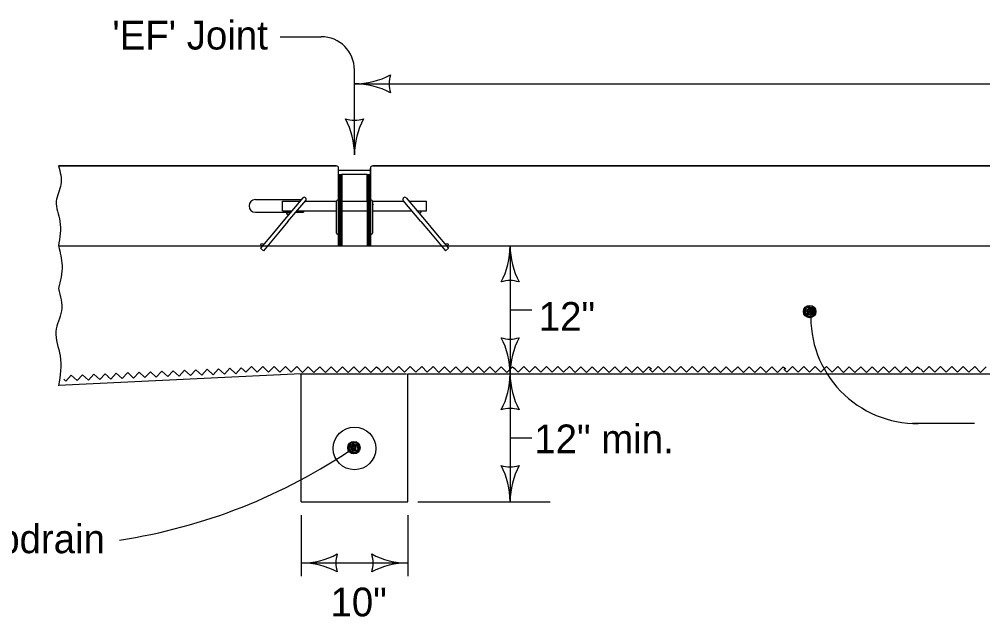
# Model space of a CAD drawing. Extents: x -2135039 to -2124495, y -2139046 to -2132546.
# Drawn here: x -2130571 to -2130034, y -2133912 to -2133579 of the extents above; entities that cross this region are included whole.
import ezdxf

# ---------------------------------------------------------------- set-up
doc = ezdxf.new("R2010")
doc.units = 0
doc.layers.add('BridgeSuperStructureExisting', color=7, linetype='Continuous')
doc.layers.add('dsnStdLabel', color=7, linetype='Continuous')

msp = doc.modelspace()

# ---------------------------------------------------------------- linework, layer by layer
at = {"layer": 'BridgeSuperStructureExisting'}
for p, q in [((-2130425.44, -2133589.02), (-2130402.65, -2133589.02)), ((-2130384.09, -2133622.52), (-2130384.09, -2133607.59)), ((-2130384.09, -2133615.29), (-2129457.45, -2133615.29)), ((-2130384.09, -2133654.91), (-2130384.09, -2133622.52)), ((-2130394.24, -2133661.05), (-2130549.09, -2133661.05)), ((-2130549.09, -2133661.05), (-2130394.24, -2133661.05)), ((-2130393, -2133680.62), (-2130393, -2133662.3)), ((-2130393, -2133692.06), (-2130393, -2133662.3)), ((-2130393, -2133663.46), (-2130375.18, -2133663.46)), ((-2130375.18, -2133662.3), (-2130375.18, -2133680.65)), ((-2130375.18, -2133692.06), (-2130375.18, -2133662.3)), ((-2129457.45, -2133661.05), (-2130373.93, -2133661.05)), ((-2130373.93, -2133661.05), (-2129457.45, -2133661.05)), ((-2130393, -2133665.86), (-2130391.21, -2133665.86)), ((-2130392.82, -2133665.86), (-2130392.82, -2133692.06)), ((-2130392.64, -2133665.86), (-2130392.64, -2133692.06)), ((-2130392.46, -2133665.86), (-2130392.46, -2133692.06)), ((-2130392.28, -2133665.86), (-2130392.28, -2133692.06)), ((-2130392.11, -2133665.86), (-2130392.11, -2133692.06)), ((-2130391.93, -2133665.86), (-2130391.93, -2133692.06)), ((-2130391.75, -2133665.86), (-2130391.75, -2133692.06)), ((-2130391.57, -2133665.86), (-2130391.57, -2133692.06)), ((-2130391.39, -2133665.86), (-2130391.39, -2133692.06)), ((-2130391.21, -2133665.86), (-2130391.21, -2133680.65)), ((-2130376.96, -2133665.86), (-2130391.21, -2133665.86)), ((-2130391.21, -2133665.86), (-2130391.21, -2133680.65)), ((-2130376.96, -2133665.86), (-2130376.96, -2133680.65)), ((-2130376.96, -2133680.65), (-2130376.96, -2133665.86)), ((-2130376.96, -2133665.86), (-2130375.18, -2133665.86)), ((-2130376.78, -2133665.86), (-2130376.78, -2133692.06)), ((-2130376.6, -2133665.86), (-2130376.6, -2133692.06)), ((-2130376.42, -2133665.86), (-2130376.42, -2133692.06)), ((-2130376.25, -2133665.86), (-2130376.25, -2133692.06)), ((-2130376.07, -2133665.86), (-2130376.07, -2133692.06)), ((-2130375.89, -2133665.86), (-2130375.89, -2133692.06)), ((-2130375.71, -2133665.86), (-2130375.71, -2133692.06)), ((-2130375.53, -2133665.86), (-2130375.53, -2133692.06)), ((-2130375.35, -2133665.86), (-2130375.35, -2133692.06)), ((-2130439.33, -2133679.76), (-2130413.63, -2133679.76)), ((-2130424.18, -2133686), (-2130424.18, -2133680.65)), ((-2130424.18, -2133680.65), (-2130414.38, -2133680.65)), ((-2130412.91, -2133678.9), (-2130423.95, -2133692.06)), ((-2130421.16, -2133692.06), (-2130411.27, -2133680.27)), ((-2130414.38, -2133680.65), (-2130414.38, -2133680.65)), ((-2130411.59, -2133680.65), (-2130394.07, -2133680.65)), ((-2130394.07, -2133698.47), (-2130394.07, -2133680.65)), ((-2130394.06, -2133698.47), (-2130394.06, -2133680.65)), ((-2130393.53, -2133680.12), (-2130393.53, -2133680.12)), ((-2130391.21, -2133680.65), (-2130391.21, -2133686)), ((-2130391.21, -2133680.65), (-2130376.96, -2133680.65)), ((-2130376.96, -2133680.65), (-2130376.96, -2133686)), ((-2130374.11, -2133680.65), (-2130374.11, -2133698.47)), ((-2130374.11, -2133698.47), (-2130374.11, -2133680.65)), ((-2130374.11, -2133680.65), (-2130356.58, -2133680.65)), ((-2130347.02, -2133692.06), (-2130356.9, -2133680.27)), ((-2130355.27, -2133678.9), (-2130344.22, -2133692.06)), ((-2130353.79, -2133680.65), (-2130353.79, -2133680.65)), ((-2130353.79, -2133680.65), (-2130343.99, -2133680.65)), ((-2130343.99, -2133686), (-2130343.99, -2133680.65)), ((-2130424.18, -2133686), (-2130418.86, -2133686)), ((-2130416.08, -2133686), (-2130394.07, -2133686)), ((-2130412.6, -2133686), (-2130412.6, -2133686.89)), ((-2130391.21, -2133686), (-2130376.96, -2133686)), ((-2130391.21, -2133686), (-2130391.21, -2133692.06)), ((-2130376.96, -2133686), (-2130376.96, -2133692.06)), ((-2130374.11, -2133681.36), (-2130374.11, -2133681.36)), ((-2130374.11, -2133686), (-2130352.1, -2133686)), ((-2130349.31, -2133686), (-2130343.99, -2133686)), ((-2130439.33, -2133686.89), (-2130419.62, -2133686.89)), ((-2130416.82, -2133686.89), (-2130412.6, -2133686.89)), ((-2130423.95, -2133692.06), (-2130429.21, -2133698.32)), ((-2130421.16, -2133692.06), (-2130426.42, -2133698.32)), ((-2130393, -2133698.32), (-2130393, -2133692.06)), ((-2130392.82, -2133692.06), (-2130392.82, -2133698.32)), ((-2130392.64, -2133692.06), (-2130392.64, -2133698.32)), ((-2130392.46, -2133692.06), (-2130392.46, -2133698.32)), ((-2130392.28, -2133692.06), (-2130392.28, -2133698.32)), ((-2130392.11, -2133692.06), (-2130392.11, -2133698.32)), ((-2130391.93, -2133692.06), (-2130391.93, -2133698.32)), ((-2130391.75, -2133692.06), (-2130391.75, -2133698.32)), ((-2130391.57, -2133692.06), (-2130391.57, -2133698.32)), ((-2130391.39, -2133692.06), (-2130391.39, -2133698.32)), ((-2130391.21, -2133692.06), (-2130391.21, -2133698.32)), ((-2130376.96, -2133692.06), (-2130376.96, -2133698.32)), ((-2130376.78, -2133692.06), (-2130376.78, -2133698.32)), ((-2130376.6, -2133692.06), (-2130376.6, -2133698.32)), ((-2130376.42, -2133692.06), (-2130376.42, -2133698.32)), ((-2130376.25, -2133692.06), (-2130376.25, -2133698.32)), ((-2130376.07, -2133692.06), (-2130376.07, -2133698.32)), ((-2130375.89, -2133692.06), (-2130375.89, -2133698.32)), ((-2130375.71, -2133692.06), (-2130375.71, -2133698.32)), ((-2130375.53, -2133692.06), (-2130375.53, -2133698.32)), ((-2130375.35, -2133692.06), (-2130375.35, -2133698.32)), ((-2130375.18, -2133698.32), (-2130375.18, -2133692.06)), ((-2130347.02, -2133692.06), (-2130341.75, -2133698.32)), ((-2130344.22, -2133692.06), (-2130338.97, -2133698.32)), ((-2130429.21, -2133698.32), (-2130436.45, -2133706.96)), ((-2130426.42, -2133698.32), (-2130434.81, -2133708.33)), ((-2130394.07, -2133698.47), (-2130394.07, -2133698.47)), ((-2130393, -2133705.6), (-2130393, -2133698.32)), ((-2130393, -2133705.6), (-2130393, -2133698.51)), ((-2130392.82, -2133698.32), (-2130392.82, -2133705.6)), ((-2130392.64, -2133698.32), (-2130392.64, -2133705.6)), ((-2130392.46, -2133698.32), (-2130392.46, -2133705.6)), ((-2130392.28, -2133698.32), (-2130392.28, -2133705.6)), ((-2130392.11, -2133698.32), (-2130392.11, -2133705.6)), ((-2130391.93, -2133698.32), (-2130391.93, -2133705.6)), ((-2130391.75, -2133698.32), (-2130391.75, -2133705.6)), ((-2130391.57, -2133698.32), (-2130391.57, -2133705.6)), ((-2130391.39, -2133698.32), (-2130391.39, -2133705.6)), ((-2130391.21, -2133698.32), (-2130391.21, -2133705.6)), ((-2130376.96, -2133698.32), (-2130376.96, -2133705.6)), ((-2130376.78, -2133698.32), (-2130376.78, -2133705.6)), ((-2130376.6, -2133698.32), (-2130376.6, -2133705.6)), ((-2130376.42, -2133698.32), (-2130376.42, -2133705.6)), ((-2130376.25, -2133698.32), (-2130376.25, -2133705.6)), ((-2130376.07, -2133698.32), (-2130376.07, -2133705.6)), ((-2130375.89, -2133698.32), (-2130375.89, -2133705.6)), ((-2130375.71, -2133698.32), (-2130375.71, -2133705.6)), ((-2130375.53, -2133698.32), (-2130375.53, -2133705.6)), ((-2130375.35, -2133698.32), (-2130375.35, -2133705.6)), ((-2130375.18, -2133705.6), (-2130375.18, -2133698.32)), ((-2130375.18, -2133698.47), (-2130375.18, -2133705.6)), ((-2130341.75, -2133698.32), (-2130333.36, -2133708.33)), ((-2130338.97, -2133698.32), (-2130331.72, -2133706.96)), ((-2130549.09, -2133705.6), (-2130432.52, -2133705.6)), ((-2130549.09, -2133705.6), (-2130435.31, -2133705.6)), ((-2130434.81, -2133708.33), (-2130436.45, -2133706.96)), ((-2130432.52, -2133705.6), (-2130393, -2133705.6)), ((-2130432.52, -2133705.6), (-2130391.21, -2133705.6)), ((-2130391.21, -2133705.6), (-2130376.96, -2133705.6)), ((-2130376.96, -2133705.6), (-2130335.65, -2133705.6)), ((-2130375.18, -2133705.6), (-2130332.86, -2133705.6)), ((-2130333.36, -2133708.33), (-2130331.72, -2133706.96)), ((-2130332.86, -2133705.6), (-2129457.45, -2133705.6)), ((-2130332.86, -2133705.6), (-2129457.45, -2133705.6)), ((-2130297.35, -2133705.6), (-2130297.35, -2133776.88)), ((-2130297.35, -2133741.24), (-2130285.23, -2133741.24)), ((-2130413.79, -2133776.88), (-2130549.09, -2133783.44)), ((-2130414.41, -2133776.88), (-2130355.01, -2133776.88)), ((-2130413.79, -2133848.16), (-2130413.79, -2133776.88)), ((-2130354.39, -2133776.88), (-2129457.45, -2133776.88)), ((-2130354.39, -2133848.16), (-2130354.39, -2133776.88)), ((-2130297.35, -2133776.88), (-2130297.35, -2133848.16)), ((-2130038.53, -2133804.61), (-2130073.08, -2133804.61)), ((-2130297.35, -2133812.52), (-2130285.23, -2133812.52)), ((-2130413.79, -2133848.16), (-2130354.39, -2133848.16)), ((-2130348.81, -2133848.16), (-2130275.01, -2133848.16)), ((-2130413.79, -2133855.59), (-2130413.79, -2133889.74)), ((-2130354.39, -2133855.59), (-2130354.39, -2133889.74)), ((-2130413.79, -2133882.32), (-2130354.39, -2133882.32))]:
    msp.add_line(p, q, dxfattribs=at)
for points in [[(-2130391.21, -2133666), (-2130391.07, -2133665.86)], [(-2130375.18, -2133680.65), (-2130375.18, -2133680.65)], [(-2130391.21, -2133686.29), (-2130390.92, -2133686)], [(-2130375.18, -2133698.47), (-2130375.18, -2133698.47)], [(-2130130.12, -2133745.4), (-2130131.29, -2133744.87), (-2130133.11, -2133744.31), (-2130133.46, -2133742.46), (-2130133.21, -2133740.84), (-2130132.05, -2133739.35), (-2130130.32, -2133739.5), (-2130128.49, -2133739.75), (-2130127.62, -2133741.21), (-2130127.46, -2133742.74), (-2130128.53, -2133744.75), (-2130129.86, -2133744.91), (-2130131.68, -2133744.45), (-2130133.18, -2133743.29), (-2130133.13, -2133741.56), (-2130131.97, -2133740.16), (-2130130.33, -2133740.01), (-2130128.51, -2133740.36), (-2130128.23, -2133741.39), (-2130127.86, -2133742.62), (-2130128.72, -2133744.13), (-2130130.05, -2133744.09), (-2130131.57, -2133743.84), (-2130132.66, -2133743), (-2130132.11, -2133741.48), (-2130130.96, -2133740.6), (-2130129.43, -2133740.54), (-2130129.05, -2133741.36), (-2130128.56, -2133742.3), (-2130129.32, -2133743.5), (-2130130.44, -2133743.77), (-2130131.45, -2133743.23), (-2130131.52, -2133742.11), (-2130130.98, -2133741.31), (-2130129.96, -2133741.03), (-2130129.46, -2133741.46), (-2130129.17, -2133742.08), (-2130129.7, -2133742.98), (-2130130.43, -2133743.16), (-2130131.13, -2133742.74), (-2130131.01, -2133742.13), (-2130130.49, -2133741.73), (-2130129.78, -2133741.75), (-2130129.79, -2133742.26), (-2130130.41, -2133742.55)], [(-2130546.19, -2133779.89), (-2130545.03, -2133780.95), (-2130542.01, -2133777.65), (-2130538.7, -2133780.68), (-2130535.67, -2133777.37), (-2130532.37, -2133780.4), (-2130529.34, -2133777.1), (-2130526.04, -2133780.13), (-2130523.01, -2133776.84), (-2130521.37, -2133778.34)], [(-2130521.52, -2133778.32), (-2130519.87, -2133779.83), (-2130516.85, -2133776.54), (-2130513.54, -2133779.57), (-2130510.51, -2133776.25), (-2130507.22, -2133779.29), (-2130504.18, -2133775.99), (-2130500.88, -2133779.01), (-2130497.85, -2133775.72), (-2130494.55, -2133778.74), (-2130491.52, -2133775.44), (-2130488.22, -2133778.47), (-2130485.2, -2133775.16), (-2130481.89, -2133778.19), (-2130478.86, -2133774.89), (-2130475.57, -2133777.92), (-2130472.53, -2133774.62), (-2130469.23, -2133777.65), (-2130466.21, -2133774.34), (-2130462.9, -2133777.38), (-2130459.87, -2133774.07), (-2130456.57, -2133777.09), (-2130453.54, -2133773.8), (-2130450.24, -2133776.82), (-2130447.21, -2133773.53), (-2130445.57, -2133775.04)], [(-2130446.28, -2133774.39), (-2130444.7, -2133775.99), (-2130441.52, -2133772.82), (-2130438.36, -2133776), (-2130435.18, -2133772.84), (-2130432.02, -2133776.02), (-2130428.85, -2133772.86), (-2130425.69, -2133776.04), (-2130422.51, -2133772.88), (-2130419.35, -2133776.06), (-2130416.17, -2133772.89), (-2130413.01, -2133776.07), (-2130409.84, -2133772.91), (-2130406.68, -2133776.09), (-2130403.5, -2133772.93), (-2130400.34, -2133776.1), (-2130397.17, -2133772.94), (-2130394.01, -2133776.12), (-2130390.84, -2133772.96), (-2130387.67, -2133776.14), (-2130384.49, -2133772.98), (-2130381.34, -2133776.15), (-2130378.16, -2133772.99), (-2130375, -2133776.18), (-2130371.83, -2133773.01), (-2130370.4, -2133774.14)], [(-2130370.41, -2133774.39), (-2130368.83, -2133775.99), (-2130365.65, -2133772.82), (-2130362.49, -2133776), (-2130359.31, -2133772.84), (-2130356.15, -2133776.02), (-2130352.98, -2133772.86), (-2130349.82, -2133776.04), (-2130346.64, -2133772.88), (-2130343.49, -2133776.06), (-2130340.3, -2133772.89), (-2130337.14, -2133776.07), (-2130333.97, -2133772.91), (-2130330.81, -2133776.09), (-2130327.63, -2133772.93), (-2130324.47, -2133776.1), (-2130321.3, -2133772.94), (-2130318.14, -2133776.12), (-2130314.97, -2133772.96), (-2130311.81, -2133776.14), (-2130308.62, -2133772.98), (-2130305.47, -2133776.15), (-2130302.3, -2133772.99), (-2130299.13, -2133776.18), (-2130295.96, -2133773.01), (-2130294.53, -2133774.14)], [(-2130294.44, -2133774.39), (-2130292.86, -2133775.99), (-2130289.68, -2133772.82), (-2130286.53, -2133776), (-2130283.34, -2133772.84), (-2130280.18, -2133776.02), (-2130277.01, -2133772.86), (-2130273.85, -2133776.04), (-2130270.67, -2133772.88), (-2130267.52, -2133776.06), (-2130264.33, -2133772.89), (-2130261.17, -2133776.07), (-2130258, -2133772.91), (-2130254.85, -2133776.09), (-2130251.66, -2133772.93), (-2130248.5, -2133776.1), (-2130245.33, -2133772.94), (-2130242.17, -2133776.12), (-2130239, -2133772.96), (-2130235.84, -2133776.14), (-2130232.65, -2133772.98), (-2130229.5, -2133776.15), (-2130226.33, -2133772.99), (-2130223.17, -2133776.18), (-2130219.99, -2133773.01), (-2130218.56, -2133774.14)], [(-2130219.6, -2133774.39), (-2130218.02, -2133775.99), (-2130214.84, -2133772.82), (-2130211.68, -2133776), (-2130208.5, -2133772.84), (-2130205.34, -2133776.02), (-2130202.17, -2133772.86), (-2130199.01, -2133776.04), (-2130195.83, -2133772.88), (-2130192.67, -2133776.06), (-2130189.49, -2133772.89), (-2130186.33, -2133776.07), (-2130183.16, -2133772.91), (-2130180, -2133776.09), (-2130176.82, -2133772.93), (-2130173.66, -2133776.1), (-2130170.49, -2133772.94), (-2130167.33, -2133776.12), (-2130164.16, -2133772.96), (-2130160.99, -2133776.14), (-2130157.81, -2133772.98), (-2130154.66, -2133776.15), (-2130151.48, -2133772.99), (-2130148.32, -2133776.18), (-2130145.15, -2133773.01), (-2130143.72, -2133774.14)], [(-2130144.7, -2133774.39), (-2130143.13, -2133775.99), (-2130139.94, -2133772.82), (-2130136.79, -2133776), (-2130133.61, -2133772.84), (-2130130.45, -2133776.02), (-2130127.28, -2133772.86), (-2130124.12, -2133776.04), (-2130120.94, -2133772.88), (-2130117.78, -2133776.06), (-2130114.6, -2133772.89), (-2130111.44, -2133776.07), (-2130108.26, -2133772.91), (-2130105.11, -2133776.09), (-2130101.93, -2133772.93), (-2130098.77, -2133776.1), (-2130095.6, -2133772.94), (-2130092.44, -2133776.12), (-2130089.26, -2133772.96), (-2130086.1, -2133776.14), (-2130082.92, -2133772.98), (-2130079.77, -2133776.15), (-2130076.59, -2133772.99), (-2130073.43, -2133776.18), (-2130070.26, -2133773.01), (-2130068.83, -2133774.14)], [(-2130068.48, -2133774.39), (-2130066.9, -2133775.99), (-2130063.72, -2133772.82), (-2130060.57, -2133776), (-2130057.38, -2133772.84), (-2130054.22, -2133776.02), (-2130051.06, -2133772.86), (-2130047.9, -2133776.04), (-2130044.71, -2133772.88), (-2130041.56, -2133776.06), (-2130038.38, -2133772.89), (-2130035.22, -2133776.07), (-2130032.04, -2133772.91)], [(-2130384.67, -2133821.24), (-2130383.49, -2133820.71), (-2130381.68, -2133820.15), (-2130381.32, -2133818.3), (-2130381.58, -2133816.69), (-2130382.74, -2133815.19), (-2130384.47, -2133815.34), (-2130386.29, -2133815.6), (-2130387.17, -2133817.05), (-2130387.33, -2133818.58), (-2130386.25, -2133820.59), (-2130384.92, -2133820.76), (-2130383.1, -2133820.29), (-2130381.61, -2133819.13), (-2130381.66, -2133817.4), (-2130382.82, -2133816.01), (-2130384.45, -2133815.85), (-2130386.27, -2133816.21), (-2130386.55, -2133817.24), (-2130386.92, -2133818.47), (-2130386.07, -2133819.98), (-2130384.74, -2133819.94), (-2130383.22, -2133819.69), (-2130382.12, -2133818.84), (-2130382.68, -2133817.33), (-2130383.83, -2133816.44), (-2130385.36, -2133816.39), (-2130385.74, -2133817.21), (-2130386.22, -2133818.14), (-2130385.47, -2133819.34), (-2130384.34, -2133819.62), (-2130383.34, -2133819.08), (-2130383.27, -2133817.96), (-2130383.8, -2133817.16), (-2130384.83, -2133816.88), (-2130385.33, -2133817.3), (-2130385.62, -2133817.92), (-2130385.08, -2133818.82), (-2130384.36, -2133819.01), (-2130383.66, -2133818.58), (-2130383.78, -2133817.97), (-2130384.3, -2133817.58), (-2130385.01, -2133817.6), (-2130385, -2133818.11), (-2130384.38, -2133818.4)]]:
    msp.add_lwpolyline(points, dxfattribs=at)
for centre, radius in [((-2130347.78, -2133686.71), 0.713), ((-2130421.14, -2133687.6), 0.713), ((-2130435.65, -2133704.89), 0.713), ((-2130332.53, -2133704.89), 0.713), ((-2130130.39, -2133742.22), 3.46), ((-2130384.09, -2133818.46), 11.88), ((-2130384.4, -2133818.06), 3.46)]:
    msp.add_circle(centre, radius, dxfattribs=at)
for centre, radius, start, end in [((-2130402.65, -2133607.58), 18.56, 0, 90), ((-2130384.09, -2133572.54), 42.75, 270, 298.0725), ((-2130348.24, -2133615.28), 16.51, 162.2666, 197.7334), ((-2130384.09, -2133658.03), 42.75, 61.9275, 90), ((-2130384.09, -2133619.06), 16.51, 252.2666, 287.7333), ((-2130426.83, -2133654.9), 42.75, 360, 28.0725), ((-2130341.34, -2133654.9), 42.75, 151.9275, 180), ((-2130394.24, -2133662.3), 1.25, 360, 90), ((-2130394.24, -2133662.3), 1.25, 0, 90), ((-2130373.93, -2133662.3), 1.25, 90, 180), ((-2130373.93, -2133662.3), 1.25, 90, 180), ((-2130439.33, -2133683.32), 3.56, 90, 270), ((-2130412.09, -2133679.58), 1.07, 320.0037, 139.9964), ((-2130393.53, -2133680.65), 0.535, 3.7252, 180), ((-2130393.53, -2133680.65), 0.535, 0, 180), ((-2130393.53, -2133680.65), 0.535, 0, 180), ((-2130374.64, -2133680.65), 0.535, 0, 180), ((-2130374.64, -2133680.65), 0.535, 0, 180), ((-2130356.08, -2133679.58), 1.07, 40.0036, 219.9963), ((-2130393.53, -2133698.47), 0.535, 180, 355.2519), ((-2130393.53, -2133698.47), 0.535, 180, 0), ((-2130374.64, -2133698.47), 0.535, 180, 0), ((-2130374.64, -2133698.47), 0.535, 180, 0), ((-2130340.09, -2133705.6), 42.75, 331.9275, 360), ((-2130340.09, -2133705.6), 42.75, 331.9275, 360), ((-2130254.6, -2133705.6), 42.75, 180, 208.0725), ((-2130254.6, -2133705.6), 42.75, 180, 208.0725), ((-2130297.35, -2133741.44), 16.51, 72.2666, 107.7334), ((-2130297.35, -2133741.44), 16.51, 72.2666, 107.7334), ((-2130070.38, -2133745.26), 59.4, 177.3942, 270.5267), ((-2130297.35, -2133741.03), 16.51, 252.2666, 287.7333), ((-2130340.09, -2133776.88), 42.75, 360, 28.0725), ((-2130297.35, -2133741.03), 16.51, 252.2666, 287.7333), ((-2130340.09, -2133776.88), 42.75, 360, 28.0725), ((-2130254.6, -2133776.88), 42.75, 151.9275, 180), ((-2130254.6, -2133776.88), 42.75, 151.9275, 180), ((-2130340.09, -2133776.88), 42.75, 331.9275, 360), ((-2130340.09, -2133776.88), 42.75, 331.9275, 360), ((-2130254.6, -2133776.88), 42.75, 180, 208.0725), ((-2130254.6, -2133776.88), 42.75, 180, 208.0725), ((-2130297.35, -2133812.72), 16.51, 72.2666, 107.7334), ((-2130297.35, -2133812.72), 16.51, 72.2666, 107.7334), ((-2130562.02, -2133558.65), 314.4, 278.602, 304.4007), ((-2130297.35, -2133812.31), 16.51, 252.2666, 287.7333), ((-2130340.09, -2133848.16), 42.75, 360, 28.0725), ((-2130297.35, -2133812.31), 16.51, 252.2666, 287.7333), ((-2130340.09, -2133848.16), 42.75, 360, 28.0725), ((-2130254.6, -2133848.16), 42.75, 151.9275, 180), ((-2130254.6, -2133848.16), 42.75, 151.9275, 180), ((-2130413.79, -2133839.57), 42.75, 270, 298.0725), ((-2130413.79, -2133839.57), 42.75, 270, 298.0725), ((-2130377.94, -2133882.31), 16.51, 162.2666, 197.7334), ((-2130377.94, -2133882.31), 16.51, 162.2666, 197.7334), ((-2130390.23, -2133882.31), 16.51, 342.2666, 17.7333), ((-2130354.39, -2133839.57), 42.75, 241.9275, 270), ((-2130390.23, -2133882.31), 16.51, 342.2666, 17.7333), ((-2130354.39, -2133839.57), 42.75, 241.9275, 270), ((-2130413.79, -2133925.06), 42.75, 61.9275, 90), ((-2130413.79, -2133925.06), 42.75, 61.9275, 90), ((-2130354.39, -2133925.06), 42.75, 90, 118.0725), ((-2130354.39, -2133925.06), 42.75, 90, 118.0725)]:
    msp.add_arc(centre, radius, start, end, dxfattribs=at)
for points in [[(-2130549.09, -2133661.05), (-2130547.73, -2133671.34), (-2130550.3, -2133680.72), (-2130548.33, -2133691.9), (-2130549.09, -2133705.6)], [(-2130549.09, -2133661.05), (-2130547.73, -2133671.34), (-2130550.3, -2133680.72), (-2130548.33, -2133691.9), (-2130549.09, -2133705.6)], [(-2130374.11, -2133681.01), (-2130374.01, -2133681.01), (-2130373.92, -2133681), (-2130373.85, -2133681.01), (-2130373.78, -2133681), (-2130373.73, -2133681.02), (-2130373.67, -2133681.01)], [(-2130374.11, -2133681.36), (-2130374.01, -2133681.37), (-2130373.92, -2133681.36), (-2130373.85, -2133681.37), (-2130373.78, -2133681.36), (-2130373.73, -2133681.38), (-2130373.67, -2133681.37)], [(-2130374.11, -2133681.72), (-2130374.01, -2133681.73), (-2130373.92, -2133681.72), (-2130373.85, -2133681.73), (-2130373.78, -2133681.71), (-2130373.73, -2133681.73), (-2130373.67, -2133681.72)], [(-2130374.11, -2133682.08), (-2130374.01, -2133682.08), (-2130373.92, -2133682.07), (-2130373.85, -2133682.08), (-2130373.78, -2133682.07), (-2130373.73, -2133682.09), (-2130373.67, -2133682.08)], [(-2130374.11, -2133682.43), (-2130374.01, -2133682.44), (-2130373.92, -2133682.43), (-2130373.85, -2133682.44), (-2130373.78, -2133682.42), (-2130373.73, -2133682.44), (-2130373.67, -2133682.44)], [(-2130374.11, -2133682.79), (-2130374.01, -2133682.8), (-2130373.92, -2133682.78), (-2130373.85, -2133682.8), (-2130373.78, -2133682.78), (-2130373.73, -2133682.8), (-2130373.67, -2133682.79)], [(-2130374.11, -2133683.15), (-2130374.01, -2133683.15), (-2130373.92, -2133683.14), (-2130373.85, -2133683.15), (-2130373.78, -2133683.14), (-2130373.73, -2133683.16), (-2130373.67, -2133683.15)], [(-2130374.11, -2133683.5), (-2130374.01, -2133683.51), (-2130373.92, -2133683.5), (-2130373.85, -2133683.51), (-2130373.78, -2133683.49), (-2130373.73, -2133683.51), (-2130373.67, -2133683.5)], [(-2130374.11, -2133683.86), (-2130374.01, -2133683.87), (-2130373.92, -2133683.85), (-2130373.85, -2133683.87), (-2130373.78, -2133683.85), (-2130373.73, -2133683.87), (-2130373.67, -2133683.86)], [(-2130374.11, -2133684.21), (-2130374.01, -2133684.22), (-2130373.92, -2133684.21), (-2130373.85, -2133684.22), (-2130373.78, -2133684.21), (-2130373.73, -2133684.23), (-2130373.67, -2133684.22)], [(-2130374.11, -2133684.57), (-2130374.01, -2133684.58), (-2130373.92, -2133684.57), (-2130373.85, -2133684.58), (-2130373.78, -2133684.56), (-2130373.73, -2133684.58), (-2130373.67, -2133684.57)], [(-2130374.11, -2133684.93), (-2130374.01, -2133684.93), (-2130373.92, -2133684.92), (-2130373.85, -2133684.93), (-2130373.78, -2133684.92), (-2130373.73, -2133684.94), (-2130373.67, -2133684.93)], [(-2130374.11, -2133685.28), (-2130374.01, -2133685.29), (-2130373.92, -2133685.28), (-2130373.85, -2133685.29), (-2130373.78, -2133685.28), (-2130373.73, -2133685.3), (-2130373.67, -2133685.29)], [(-2130374.11, -2133685.64), (-2130374.01, -2133685.65), (-2130373.92, -2133685.64), (-2130373.85, -2133685.65), (-2130373.78, -2133685.63), (-2130373.73, -2133685.65), (-2130373.67, -2133685.64)], [(-2130549.09, -2133705.6), (-2130547.12, -2133716.54), (-2130549.09, -2133729.36)], [(-2130549.09, -2133729.36), (-2130547.44, -2133741.87), (-2130550.56, -2133753.26), (-2130548.17, -2133766.86), (-2130549.09, -2133783.51)]]:
    msp.add_spline(points, degree=3, dxfattribs=at)

# ---------------------------------------------------------------- texts
at = {"layer": 'dsnStdLabel'}
for s, p in [("'EF' Joint", (-2130519.06, -2133596.16)), ('12"', (-2130281.37, -2133752.9)), ('12" min.', (-2130283.88, -2133821.15)), ('4" Perforated Subdrain', (-2130740.13, -2133876.86)), ('10"', (-2130397.47, -2133912.04))]:
    msp.add_text(s, height=16, dxfattribs=at).set_placement(p)

doc.saveas('drawing.dxf')
